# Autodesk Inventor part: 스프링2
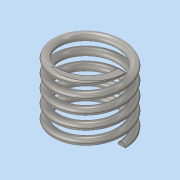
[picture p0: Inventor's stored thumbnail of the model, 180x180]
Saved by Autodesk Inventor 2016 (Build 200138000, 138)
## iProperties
Created: 2019-11
Part Number: 스프링2
Material: 스테인레스 스틸
Document SubType Name: Modeling
Designer: user
Density: 8 g/cm^3
Appearance: 반연마
Mass: 6.55763 g
Surface Area: 16.7052 cm^2
Volume: 0.819704 cm^3
Author: user
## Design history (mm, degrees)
sketch "스케치1"
  geometry: L1 (0, 0)-(8.5, 0); L2 (8.5, 0)-(8.5, 17.5); L3 (8.5, 17.5)-(0, 17.5); L4 (0, 17.5)-(0, 0); C1 r 1 at (8.5, 0)
  constraints: 8 end point, 2 parallel, 1 centre point, 1 coincident, 1 horizontal, 1 perpendicular
  dimensions: "d0" = 17 diameter of L2 L4; "d1" = 17.5 distance between parallel lines of L1 L3 (derived); "d2" = 2 diameter of C1
feature "코일1" sketch "스케치1" pitch "d3" = 10; turns "d5" = 5; dims "d4" = 17.5 (= d1), "d6" = 0, angle "d7" = 90 deg, angle "d8" = 90 deg, "d9" = 0, "d10" = 0
sketch "스케치2"
  geometry: L1 (17.5, 11.695)-(0, 11.695); L2 (0, 11.695)-(0, -11.695); L3 (0, -11.695)-(17.5, -11.695); L4 (17.5, -11.695)-(17.5, 11.695); 2 further points
  constraints: 8 end point, 2 parallel, 1 coincident, 1 horizontal, 1 midpoint, 1 perpendicular
  dimensions: "d11" = 17.5 distance between parallel lines of L2 L4 (= d1)
extrude "돌출1" sketch "스케치2" stored distance "d12" = 42; taper "d13" = 0 deg
node "솔리드1"
